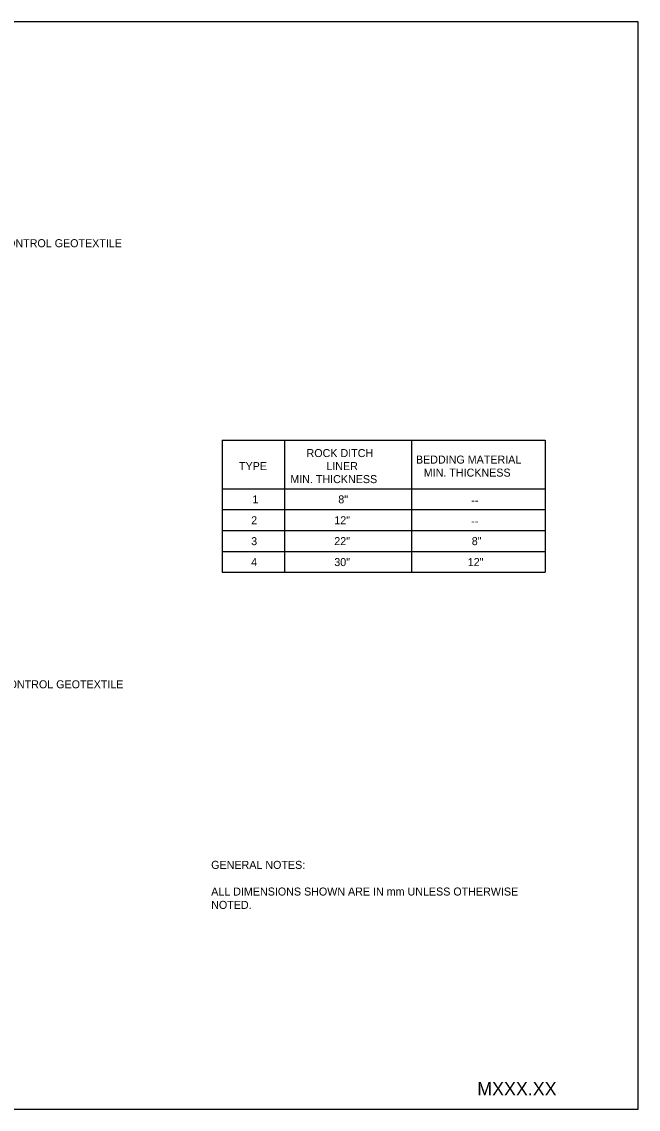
# Model space of a CAD drawing. Extents: x -439.1 to -407.9, y -458.1 to -436.2.
# Drawn here: x -419.41 to -407.86, y -458.05 to -437.68 of the extents above; entities that cross this region are included whole.
import ezdxf

# ---------------------------------------------------------------- set-up
doc = ezdxf.new("R2010")
doc.units = 0
for name, color, linetype in [('Default', 7, 'Continuous'), ('Draft_Named_Boundary', 7, 'Continuous'), ('Level 4', 7, 'Continuous'), ('Level 46', 7, 'Continuous')]:
    doc.layers.add(name, color=color, linetype=linetype)

msp = doc.modelspace()

# ---------------------------------------------------------------- linework, layer by layer
at = {"layer": 'Draft_Named_Boundary'}
msp.add_lwpolyline([(-439.109, -458.051), (-407.859, -458.051), (-407.859, -437.676), (-439.109, -437.676)], close=True, dxfattribs=at)
at = {"layer": 'Level 4'}
for p, q in [((-415.651, -445.518), (-409.604, -445.518)), ((-415.651, -445.518), (-415.651, -447.991)), ((-414.483, -445.518), (-414.483, -447.991)), ((-412.104, -445.518), (-412.104, -447.991)), ((-409.604, -445.518), (-409.604, -447.991)), ((-415.651, -446.424), (-409.604, -446.424)), ((-415.651, -446.816), (-409.604, -446.816)), ((-415.651, -447.208), (-409.604, -447.208)), ((-415.651, -447.6), (-409.604, -447.6)), ((-415.651, -447.991), (-409.604, -447.991))]:
    msp.add_line(p, q, dxfattribs=at)

# ---------------------------------------------------------------- texts
at = {"layer": 'Default'}
for p in [(-420.808, -441.9), (-420.78, -450.164)]:
    msp.add_text('EROSION CONTROL GEOTEXTILE', height=0.15, dxfattribs=at).set_placement(p)
at = {"layer": 'Level 4'}
for s, p in [('ROCK DITCH', (-414.073, -445.832)), ('BEDDING MATERIAL', (-412.023, -445.954)), ('TYPE', (-415.338, -446.076)), ('LINER', (-413.702, -446.076)), ('MIN. THICKNESS', (-414.377, -446.32)), ('MIN. THICKNESS', (-411.877, -446.198)), ('1', (-415.087, -446.699)), ('8"', (-413.478, -446.699)), ('--', (-410.986, -446.714)), ('2', (-415.11, -447.091)), ('12"', (-413.553, -447.091)), ('--', (-410.986, -447.106)), ('3', (-415.11, -447.482)), ('22"', (-413.553, -447.482)), ('8"', (-410.978, -447.482)), ('4', (-415.11, -447.874)), ('30"', (-413.553, -447.874)), ('12"', (-411.053, -447.874))]:
    msp.add_text(s, height=0.15, dxfattribs=at).set_placement(p)
at = {"layer": 'Level 46'}
for s, height, p in [('GENERAL NOTES:', 0.15, (-415.859, -453.547)), ('ALL DIMENSIONS SHOWN ARE IN mm UNLESS OTHERWISE ', 0.15, (-415.859, -454.047)), ('NOTED.', 0.15, (-415.859, -454.297)), ('MXXX.XX', 0.25, (-410.875, -457.792))]:
    msp.add_text(s, height=height, dxfattribs=at).set_placement(p)

doc.saveas('drawing.dxf')
